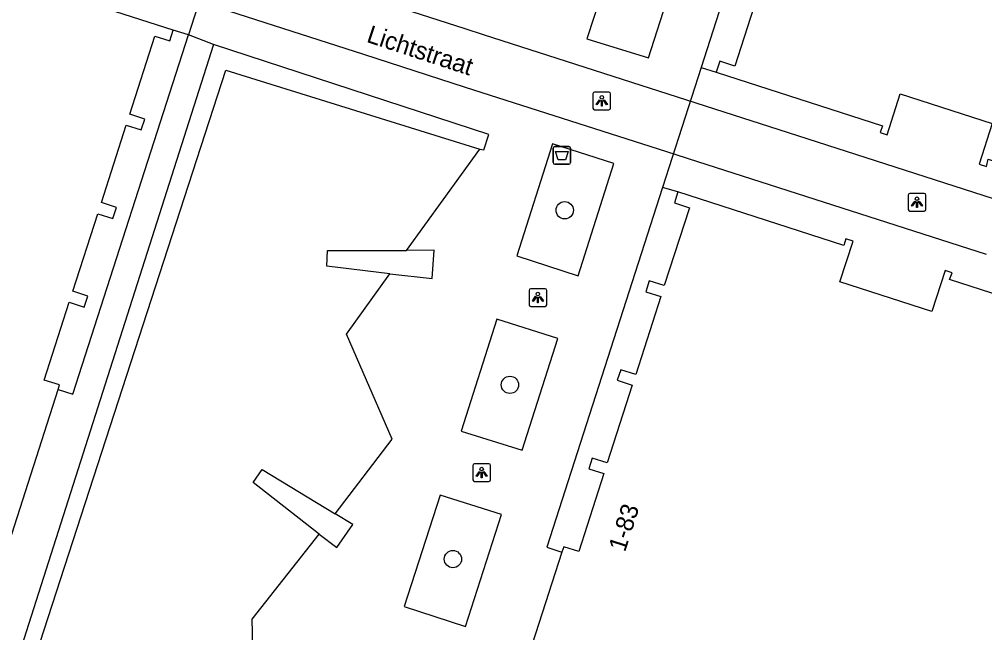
# Model space of a CAD drawing. Extents: x 160676 to 161153, y 383244 to 383713.
# Drawn here: x 160880.9 to 160935.4, y 383286.2 to 383320.8 of the extents above; entities that cross this region are included whole.
import ezdxf

# ---------------------------------------------------------------- set-up
doc = ezdxf.new("R2010")
doc.units = 0
for name, color, linetype in [('IMGEO_Afvalbak', 7, 'Continuous'), ('IMGEO_Boom', 7, 'Continuous'), ('IMGEO_Lichtpunt', 7, 'Continuous'), ('IMGEO_Lijnafwatering', 7, 'Continuous'), ('IMGEO_Muur', 7, 'Continuous'), ('IMGEO_Openbare_ruimte_label', 7, 'Continuous'), ('IMGEO_Pand', 7, 'Continuous'), ('IMGEO_Pand_nummerreeks', 7, 'Continuous'), ('IMGEO_Voetpad_open', 7, 'Continuous')]:
    doc.layers.add(name, color=color, linetype=linetype)

msp = doc.modelspace()

# ---------------------------------------------------------------- linework, layer by layer
at = {"layer": 'IMGEO_Afvalbak'}
for p, q in [((160911.007, 383312.712), (160911.007, 383313.512)), ((160911.007, 383313.512), (160911.007, 383312.712)), ((160911.107, 383313.612), (160911.897, 383313.612)), ((160911.897, 383313.612), (160911.107, 383313.612)), ((160911.997, 383313.512), (160911.997, 383312.712)), ((160911.997, 383312.712), (160911.997, 383313.512)), ((160911.897, 383312.612), (160911.107, 383312.612)), ((160911.107, 383312.612), (160911.897, 383312.612))]:
    msp.add_line(p, q, dxfattribs=at)
msp.add_lwpolyline([(160911.15, 383313.326), (160911.854, 383313.326), (160911.705, 383312.856), (160911.299, 383312.856), (160911.15, 383313.326)], dxfattribs=at)
for centre, start, end in [((160911.107, 383313.512), 90, 180), ((160911.107, 383313.512), 90, 180), ((160911.897, 383313.512), 0, 90), ((160911.897, 383313.512), 360, 90), ((160911.107, 383312.712), 180, 270), ((160911.107, 383312.712), 180, 270), ((160911.897, 383312.712), 270, 0), ((160911.897, 383312.712), 270, 0)]:
    msp.add_arc(centre, 0.1, start, end, dxfattribs=at)
at = {"layer": 'IMGEO_Boom'}
for centre in [(160911.662, 383310.017), (160908.57, 383300.159), (160905.349, 383290.319)]:
    msp.add_circle(centre, 0.489, dxfattribs=at)
at = {"layer": 'IMGEO_Lichtpunt'}
for p, q in [((160913.259, 383316.592), (160913.259, 383315.785)), ((160913.259, 383316.592), (160913.259, 383315.785)), ((160914.161, 383316.687), (160913.353, 383316.687)), ((160914.161, 383316.687), (160913.353, 383316.687)), ((160914.255, 383315.785), (160914.255, 383316.592)), ((160914.255, 383315.785), (160914.255, 383316.592)), ((160913.353, 383315.691), (160914.161, 383315.691)), ((160913.353, 383315.691), (160914.161, 383315.691)), ((160931.056, 383310.869), (160931.056, 383310.062)), ((160931.056, 383310.869), (160931.056, 383310.062)), ((160931.958, 383310.964), (160931.15, 383310.964)), ((160931.958, 383310.964), (160931.15, 383310.964)), ((160932.052, 383310.062), (160932.052, 383310.869)), ((160932.052, 383310.062), (160932.052, 383310.869)), ((160931.15, 383309.968), (160931.958, 383309.968)), ((160931.15, 383309.968), (160931.958, 383309.968)), ((160909.649, 383305.492), (160909.649, 383304.685)), ((160909.649, 383305.492), (160909.649, 383304.685)), ((160910.551, 383305.587), (160909.743, 383305.587)), ((160910.551, 383305.587), (160909.743, 383305.587)), ((160910.645, 383304.685), (160910.645, 383305.492)), ((160910.645, 383304.685), (160910.645, 383305.492)), ((160909.743, 383304.591), (160910.551, 383304.591)), ((160909.743, 383304.591), (160910.551, 383304.591)), ((160906.48, 383295.607), (160906.48, 383294.8)), ((160906.48, 383295.607), (160906.48, 383294.8)), ((160907.382, 383295.702), (160906.574, 383295.702)), ((160907.382, 383295.702), (160906.574, 383295.702)), ((160907.476, 383294.8), (160907.476, 383295.607)), ((160907.476, 383294.8), (160907.476, 383295.607)), ((160906.574, 383294.706), (160907.382, 383294.706)), ((160906.574, 383294.706), (160907.382, 383294.706))]:
    msp.add_line(p, q, dxfattribs=at)
for points in [[(160913.633, 383316.256), (160913.672, 383316.228), (160913.484, 383315.966), (160913.446, 383315.993), (160913.633, 383316.256)], [(160913.735, 383316.208), (160913.782, 383316.208), (160913.782, 383315.886), (160913.735, 383315.886), (160913.735, 383316.208)], [(160913.845, 383316.228), (160913.883, 383316.255), (160914.07, 383315.993), (160914.031, 383315.965), (160913.845, 383316.228)], [(160931.43, 383310.533), (160931.469, 383310.505), (160931.281, 383310.243), (160931.243, 383310.27), (160931.43, 383310.533)], [(160931.532, 383310.485), (160931.579, 383310.485), (160931.579, 383310.163), (160931.532, 383310.163), (160931.532, 383310.485)], [(160931.642, 383310.505), (160931.68, 383310.532), (160931.867, 383310.27), (160931.828, 383310.242), (160931.642, 383310.505)], [(160910.023, 383305.156), (160910.062, 383305.128), (160909.874, 383304.866), (160909.836, 383304.893), (160910.023, 383305.156)], [(160910.125, 383305.108), (160910.172, 383305.108), (160910.172, 383304.786), (160910.125, 383304.786), (160910.125, 383305.108)], [(160910.235, 383305.128), (160910.273, 383305.155), (160910.46, 383304.893), (160910.421, 383304.865), (160910.235, 383305.128)], [(160906.854, 383295.271), (160906.893, 383295.243), (160906.705, 383294.981), (160906.667, 383295.008), (160906.854, 383295.271)], [(160906.956, 383295.223), (160907.003, 383295.223), (160907.003, 383294.901), (160906.956, 383294.901), (160906.956, 383295.223)], [(160907.066, 383295.243), (160907.104, 383295.27), (160907.291, 383295.008), (160907.252, 383294.98), (160907.066, 383295.243)]]:
    msp.add_lwpolyline(points, dxfattribs=at)
for centre in [(160913.758, 383316.39), (160931.555, 383310.667), (160910.148, 383305.29), (160906.979, 383295.405)]:
    msp.add_circle(centre, 0.0994, dxfattribs=at)
for centre, start, end in [((160913.353, 383316.592), 90, 180), ((160913.353, 383316.592), 90, 180), ((160914.161, 383316.592), 0, 90), ((160914.161, 383316.592), 0, 90), ((160913.353, 383315.785), 180, 270), ((160913.353, 383315.785), 180, 270), ((160914.161, 383315.785), 270, 0), ((160914.161, 383315.785), 270, 360), ((160931.15, 383310.869), 90, 180), ((160931.15, 383310.869), 90, 180), ((160931.958, 383310.869), 0, 90), ((160931.958, 383310.869), 0, 90), ((160931.15, 383310.062), 180, 270), ((160931.15, 383310.062), 180, 270), ((160931.958, 383310.062), 270, 0), ((160931.958, 383310.062), 270, 360), ((160909.743, 383305.492), 90, 180), ((160909.743, 383305.492), 90, 180), ((160910.551, 383305.492), 0, 90), ((160910.551, 383305.492), 0, 90), ((160909.743, 383304.685), 180, 270), ((160909.743, 383304.685), 180, 270), ((160910.551, 383304.685), 270, 0), ((160910.551, 383304.685), 270, 360), ((160906.574, 383295.607), 90, 180), ((160906.574, 383295.607), 90, 180), ((160907.382, 383295.607), 0, 90), ((160907.382, 383295.607), 0, 90), ((160906.574, 383294.8), 180, 270), ((160906.574, 383294.8), 180, 270), ((160907.382, 383294.8), 270, 0), ((160907.382, 383294.8), 270, 360)]:
    msp.add_arc(centre, 0.0946, start, end, dxfattribs=at)
at = {"layer": 'IMGEO_Lijnafwatering'}
for points in [[(160906.05, 383320.254), (160891.14, 383325.048), (160887.278, 383326.29)], [(160900.324, 383318.808), (160890.178, 383322.078), (160882.755, 383324.471)], [(160924.823, 383314.218), (160919.605, 383315.896), (160907.077, 383319.924), (160906.05, 383320.254)], [(160917.898, 383313.159), (160906.071, 383316.955), (160900.324, 383318.808)], [(160943.595, 383308.182), (160924.823, 383314.218)], [(160935.473, 383307.516), (160918.647, 383312.918), (160917.898, 383313.159)]]:
    msp.add_lwpolyline(points, dxfattribs=at)
at = {"layer": 'IMGEO_Muur'}
for points in [[(160935.274, 383367.567), (160919.362, 383318.078), (160920.218, 383317.803)], [(160883.064, 383299.902), (160883.899, 383299.633), (160890.43, 383319.911), (160889.564, 383320.185)], [(160891.841, 383319.364), (160878.327, 383277.067)], [(160906.876, 383313.464), (160907.093, 383313.431), (160907.377, 383314.301), (160891.841, 383319.364)], [(160894.225, 383275.803), (160879.452, 383277.685), (160892.534, 383317.918), (160906.876, 383313.464)], [(160918.048, 383311.056), (160917.177, 383311.305), (160910.659, 383290.993), (160911.5, 383290.712)]]:
    msp.add_lwpolyline(points, dxfattribs=at)
at = {"layer": 'IMGEO_Pand'}
for points in [[(160889.564, 383320.185), (160880.203, 383323.201), (160880.326, 383323.579), (160879.916, 383323.714), (160879.174, 383321.41), (160873.984, 383323.076), (160874.726, 383325.379), (160874.318, 383325.508), (160874.197, 383325.127), (160864.867, 383328.119)], [(160922.68, 383322.556), (160921.263, 383318.153), (160920.415, 383318.424), (160920.218, 383317.803)], [(160883.064, 383299.902), (160883.144, 383300.154), (160882.28, 383300.43), (160883.691, 383304.823), (160884.539, 383304.552), (160884.745, 383305.172), (160883.897, 383305.443), (160885.297, 383309.822), (160886.145, 383309.551), (160886.357, 383310.175), (160885.509, 383310.446), (160886.912, 383314.821), (160887.76, 383314.55), (160887.954, 383315.162), (160887.106, 383315.433), (160888.522, 383319.848), (160889.37, 383319.577), (160889.564, 383320.185)], [(160920.218, 383317.803), (160929.595, 383314.788), (160929.466, 383314.412), (160929.868, 383314.28), (160930.61, 383316.584), (160935.799, 383314.916), (160935.057, 383312.612), (160935.469, 383312.483), (160935.57, 383312.891), (160944.96, 383309.85)], [(160918.048, 383311.056), (160917.856, 383310.432), (160918.704, 383310.161), (160917.284, 383305.764), (160916.436, 383306.035), (160916.244, 383305.411), (160917.092, 383305.14), (160915.672, 383300.743), (160914.824, 383301.014), (160914.625, 383300.421), (160915.473, 383300.15), (160914.068, 383295.753), (160913.22, 383296.024), (160913.025, 383295.418), (160913.873, 383295.147), (160912.461, 383290.743), (160911.613, 383291.014), (160911.5, 383290.712)], [(160942.777, 383303.077), (160933.386, 383306.103), (160933.536, 383306.474), (160933.134, 383306.606), (160932.393, 383304.302), (160927.197, 383305.975), (160927.939, 383308.279), (160927.536, 383308.411), (160927.414, 383308.031), (160918.048, 383311.056)], [(160877.358, 383282.151), (160883.064, 383299.902)], [(160911.5, 383290.712), (160907.414, 383278.054)]]:
    msp.add_lwpolyline(points, dxfattribs=at)
at = {"layer": 'IMGEO_Voetpad_open'}
for points in [[(160935.274, 383367.567), (160919.362, 383318.078)], [(160892.596, 383326.678), (160890.43, 383319.911)], [(160916.399, 383318.618), (160918.408, 383324.902), (160914.982, 383326.017), (160912.907, 383319.7), (160916.399, 383318.618)], [(160890.43, 383319.911), (160889.564, 383320.185)], [(160883.064, 383299.902), (160883.899, 383299.633), (160890.43, 383319.911)], [(160891.841, 383319.364), (160890.43, 383319.911)], [(160919.362, 383318.078), (160917.177, 383311.305)], [(160919.362, 383318.078), (160920.218, 383317.803)], [(160902.729, 383307.742), (160906.876, 383313.464)], [(160912.419, 383306.316), (160914.43, 383312.651), (160910.976, 383313.76), (160908.966, 383307.435), (160912.419, 383306.316)], [(160917.177, 383311.305), (160910.659, 383290.993), (160911.5, 383290.712)], [(160918.048, 383311.056), (160917.177, 383311.305)], [(160901.796, 383306.424), (160898.231, 383306.858), (160898.279, 383307.748), (160902.729, 383307.742)], [(160901.796, 383306.424), (160904.189, 383306.165), (160904.287, 383307.753), (160902.729, 383307.742)], [(160898.704, 383292.874), (160901.927, 383297.09), (160899.352, 383303.027), (160901.796, 383306.424)], [(160909.257, 383296.465), (160911.267, 383302.776), (160907.831, 383303.875), (160905.814, 383297.542), (160909.257, 383296.465)], [(160897.799, 383291.735), (160894.077, 383294.652), (160894.581, 383295.388), (160898.704, 383292.874)], [(160906.059, 383286.522), (160908.095, 383292.835), (160904.631, 383293.937), (160902.598, 383287.637), (160906.059, 383286.522)], [(160897.799, 383291.735), (160898.798, 383290.979), (160899.697, 383292.282), (160898.704, 383292.874)], [(160894.127, 383282.233), (160894.015, 383286.93), (160897.799, 383291.735)]]:
    msp.add_lwpolyline(points, dxfattribs=at)

# ---------------------------------------------------------------- texts
at = {"layer": 'IMGEO_Openbare_ruimte_label'}
msp.add_text('Lichtstraat', height=1, rotation=341.891, dxfattribs=at).set_placement((160900.423, 383319.53))
at = {"layer": 'IMGEO_Pand_nummerreeks'}
msp.add_text('1-83', height=1, rotation=72.2213, dxfattribs=at).set_placement((160915.066, 383290.682))

doc.saveas('drawing.dxf')
